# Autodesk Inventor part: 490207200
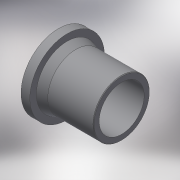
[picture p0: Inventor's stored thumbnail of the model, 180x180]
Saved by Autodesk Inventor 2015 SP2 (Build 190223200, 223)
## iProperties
Created: 2017-07
Part Number: 490207200
Material: Generic
Description: Stub Flange 200
Document SubType Name: Modeling
Designer: Кирилл
Mass: 3220.47 g
Surface Area: 3055.82 cm^2
Volume: 3220.47 cm^3
Density: 1 g/cm^3
Appearance: Default
Author: Кирилл
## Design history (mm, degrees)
derived "490207.ipt"
feature "Solid1::490207.ipt"
tag "TaggingFeature1"
body "Solid1"
other parameters: "d1" = 232, "d4" = 268, "d5" = 32, "d6" = 135, "d17" = 4, "d18" = 4, "d19" = 4, "d21" = 4, "d24" = 4, "d25" = 4, "d26" = 2, "d27" = 0, "d32" = 2, "L_1" = 135, "D_" = 268, "D_1" = 232, "a_" = 32
